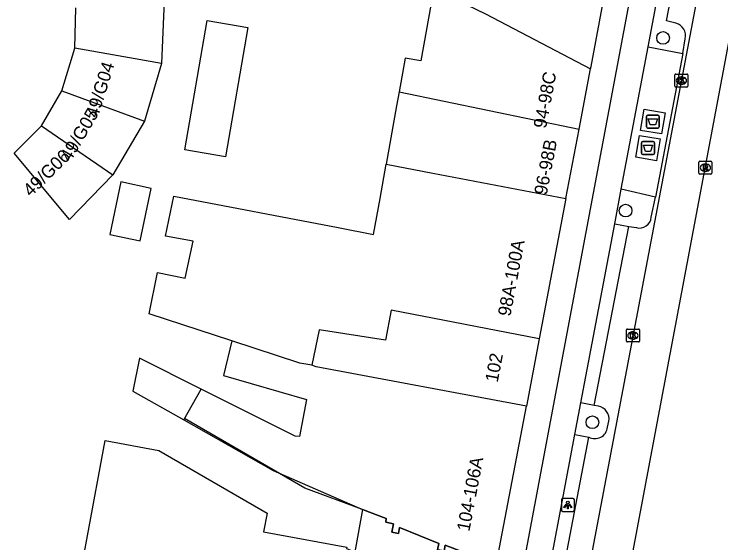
# Model space of a CAD drawing. Extents: x 161402 to 161933, y 381650 to 382313.
# Drawn here: x 161821 to 161875.5, y 381796.3 to 381837.1 of the extents above; entities that cross this region are included whole.
import ezdxf

# ---------------------------------------------------------------- set-up
doc = ezdxf.new("R2010")
doc.units = 0
for name, color, linetype in [('IMGEO_Afval_apart_plaats', 7, 'Continuous'), ('IMGEO_Berm_open', 7, 'Continuous'), ('IMGEO_Boom', 7, 'Continuous'), ('IMGEO_Fietspad_gesloten', 7, 'Continuous'), ('IMGEO_Hek', 7, 'Continuous'), ('IMGEO_Kolk', 7, 'Continuous'), ('IMGEO_Lichtpunt', 7, 'Continuous'), ('IMGEO_OVBaan_gesloten', 7, 'Continuous'), ('IMGEO_Pand', 7, 'Continuous'), ('IMGEO_Pand_nummerreeks', 7, 'Continuous'), ('IMGEO_Pand_overbouw', 7, 'Continuous'), ('IMGEO_Parkeervlak_open', 7, 'Continuous'), ('IMGEO_Rijbaan_lokaal_gesloten', 7, 'Continuous'), ('IMGEO_Rioolput', 7, 'Continuous'), ('IMGEO_Voetpad_gesloten', 7, 'Continuous'), ('IMGEO_Voetpad_open', 7, 'Continuous')]:
    doc.layers.add(name, color=color, linetype=linetype)

msp = doc.modelspace()

# ---------------------------------------------------------------- linework, layer by layer
at = {"layer": 'IMGEO_Afval_apart_plaats'}
for p, q in [((161869.774, 381828.434), (161869.774, 381829.234)), ((161869.774, 381829.234), (161869.774, 381828.434)), ((161869.874, 381829.334), (161870.664, 381829.334)), ((161870.664, 381829.334), (161869.874, 381829.334)), ((161870.764, 381829.234), (161870.764, 381828.434)), ((161870.764, 381828.434), (161870.764, 381829.234)), ((161870.664, 381828.334), (161869.874, 381828.334)), ((161869.874, 381828.334), (161870.664, 381828.334)), ((161869.4, 381826.391), (161869.4, 381827.191)), ((161869.4, 381827.191), (161869.4, 381826.391)), ((161869.5, 381827.291), (161870.29, 381827.291)), ((161870.29, 381827.291), (161869.5, 381827.291)), ((161870.39, 381827.191), (161870.39, 381826.391)), ((161870.39, 381826.391), (161870.39, 381827.191)), ((161870.29, 381826.291), (161869.5, 381826.291)), ((161869.5, 381826.291), (161870.29, 381826.291))]:
    msp.add_line(p, q, dxfattribs=at)
for points in [[(161869.917, 381829.048), (161870.621, 381829.048), (161870.472, 381828.578), (161870.066, 381828.578), (161869.917, 381829.048)], [(161869.543, 381827.005), (161870.247, 381827.005), (161870.098, 381826.535), (161869.692, 381826.535), (161869.543, 381827.005)]]:
    msp.add_lwpolyline(points, dxfattribs=at)
for centre, start, end in [((161869.874, 381829.234), 90, 180), ((161869.874, 381829.234), 90, 180), ((161870.664, 381829.234), 0, 90), ((161870.664, 381829.234), 360, 90), ((161869.874, 381828.434), 180, 270), ((161869.874, 381828.434), 180, 270), ((161870.664, 381828.434), 270, 0), ((161870.664, 381828.434), 270, 0), ((161869.5, 381827.191), 90, 180), ((161869.5, 381827.191), 90, 180), ((161870.29, 381827.191), 0, 90), ((161870.29, 381827.191), 360, 90), ((161869.5, 381826.391), 180, 270), ((161869.5, 381826.391), 180, 270), ((161870.29, 381826.391), 270, 0), ((161870.29, 381826.391), 270, 0)]:
    msp.add_arc(centre, 0.1, start, end, dxfattribs=at)
at = {"layer": 'IMGEO_Berm_open'}
for points in [[(161867.323, 381820.954), (161868.41, 381820.749)], [(161865.742, 381806.939), (161864.714, 381807.133)], [(161864.254, 381804.698), (161865.316, 381804.498)]]:
    msp.add_lwpolyline(points, dxfattribs=at)
at = {"layer": 'IMGEO_Boom'}
for centre in [(161871.055, 381835.287), (161868.169, 381821.967), (161865.604, 381805.641)]:
    msp.add_circle(centre, 0.489, dxfattribs=at)
at = {"layer": 'IMGEO_Fietspad_gesloten'}
for points in [[(161869.899, 381834.602), (161881.54, 381896.271), (161882.623, 381902.093), (161888.398, 381933.147), (161890.059, 381942.083), (161900.83, 382000), (161908.061, 382038.88), (161912.039, 382060.567)], [(161886.669, 381935.154), (161880.56, 381902.497), (161879.486, 381896.758), (161857.65, 381780.798), (161851.928, 381750), (161842.232, 381697.819)], [(161867.824, 381823.608), (161869.899, 381834.602)], [(161867.323, 381820.954), (161867.824, 381823.608)], [(161864.714, 381807.133), (161867.323, 381820.954)], [(161864.254, 381804.698), (161864.714, 381807.133)], [(161844.249, 381697.445), (161849.541, 381725.922), (161850.643, 381731.85), (161854.016, 381750), (161859.509, 381779.56), (161864.254, 381804.698)]]:
    msp.add_lwpolyline(points, dxfattribs=at)
at = {"layer": 'IMGEO_Hek'}
msp.add_lwpolyline([(161847.86, 381798.902), (161843.405, 381800.565), (161834.122, 381805.937)], dxfattribs=at)
at = {"layer": 'IMGEO_Kolk'}
for p, q in [((161871.971, 381831.573), (161871.971, 381832.425)), ((161872.046, 381832.499), (161872.898, 381832.499)), ((161872.972, 381832.425), (161872.972, 381831.573)), ((161872.459, 381832.279), (161872.484, 381832.279)), ((161872.898, 381831.499), (161872.046, 381831.499)), ((161872.482, 381831.719), (161872.457, 381831.719)), ((161868.225, 381811.906), (161868.225, 381812.758)), ((161868.3, 381812.832), (161869.152, 381812.832)), ((161869.226, 381812.758), (161869.226, 381811.906)), ((161868.713, 381812.612), (161868.738, 381812.612)), ((161869.152, 381811.832), (161868.3, 381811.832)), ((161868.736, 381812.052), (161868.711, 381812.052))]:
    msp.add_line(p, q, dxfattribs=at)
for points in [[(161871.971, 381831.573), (161871.971, 381832.425)], [(161872.046, 381832.499), (161872.898, 381832.499)], [(161872.972, 381832.425), (161872.972, 381831.573)], [(161872.292, 381832.199), (161872.415, 381832.199), (161872.415, 381832.048), (161872.545, 381832.199), (161872.709, 381832.199), (161872.563, 381832.048), (161872.716, 381831.799), (161872.564, 381831.799), (161872.479, 381831.963), (161872.415, 381831.896), (161872.415, 381831.799), (161872.292, 381831.799), (161872.292, 381832.199)], [(161872.898, 381831.499), (161872.046, 381831.499)], [(161868.225, 381811.906), (161868.225, 381812.758)], [(161868.3, 381812.832), (161869.152, 381812.832)], [(161869.226, 381812.758), (161869.226, 381811.906)], [(161868.546, 381812.532), (161868.669, 381812.532), (161868.669, 381812.381), (161868.799, 381812.532), (161868.963, 381812.532), (161868.817, 381812.381), (161868.97, 381812.132), (161868.818, 381812.132), (161868.733, 381812.296), (161868.669, 381812.229), (161868.669, 381812.132), (161868.546, 381812.132), (161868.546, 381812.532)], [(161869.152, 381811.832), (161868.3, 381811.832)]]:
    msp.add_lwpolyline(points, dxfattribs=at)
for centre, start, end in [((161872.048, 381832.423), 91.552, 178.448), ((161872.048, 381832.423), 91.552, 178.448), ((161872.896, 381832.423), 1.552, 88.448), ((161872.896, 381832.423), 1.552, 88.448), ((161872.048, 381831.575), 181.552, 268.448), ((161872.048, 381831.575), 181.552, 268.448), ((161872.896, 381831.575), 271.552, 358.448), ((161872.896, 381831.575), 271.552, 358.448), ((161868.302, 381812.756), 91.552, 178.448), ((161868.302, 381812.756), 91.552, 178.448), ((161869.15, 381812.756), 1.552, 88.448), ((161869.15, 381812.756), 1.552, 88.448), ((161868.302, 381811.908), 181.552, 268.448), ((161868.302, 381811.908), 181.552, 268.448), ((161869.15, 381811.908), 271.552, 358.448), ((161869.15, 381811.908), 271.552, 358.448)]:
    msp.add_arc(centre, 0.0765, start, end, dxfattribs=at)
for centre, major_axis, ratio, start_param, end_param in [((161872.458, 381831.999), (-0.387, 0.002), 0.722429, 4.712389, 7.853982), ((161872.483, 381831.999), (-0.39, 0.002), 0.717154, 1.570796, 4.712389), ((161868.712, 381812.332), (-0.387, 0.002), 0.722429, 4.712389, 7.853982), ((161868.737, 381812.332), (-0.39, 0.002), 0.717154, 1.570796, 4.712389)]:
    msp.add_ellipse(centre, major_axis=major_axis, ratio=ratio, start_param=start_param, end_param=end_param, dxfattribs=at)
at = {"layer": 'IMGEO_Lichtpunt'}
for p, q in [((161863.212, 381799.659), (161863.212, 381798.852)), ((161863.212, 381799.659), (161863.212, 381798.852)), ((161864.114, 381799.754), (161863.306, 381799.754)), ((161864.114, 381799.754), (161863.306, 381799.754)), ((161864.208, 381798.852), (161864.208, 381799.659)), ((161864.208, 381798.852), (161864.208, 381799.659)), ((161863.306, 381798.758), (161864.114, 381798.758)), ((161863.306, 381798.758), (161864.114, 381798.758))]:
    msp.add_line(p, q, dxfattribs=at)
for points in [[(161863.586, 381799.323), (161863.625, 381799.295), (161863.437, 381799.033), (161863.399, 381799.06), (161863.586, 381799.323)], [(161863.688, 381799.275), (161863.735, 381799.275), (161863.735, 381798.953), (161863.688, 381798.953), (161863.688, 381799.275)], [(161863.798, 381799.295), (161863.836, 381799.322), (161864.023, 381799.06), (161863.984, 381799.032), (161863.798, 381799.295)]]:
    msp.add_lwpolyline(points, dxfattribs=at)
msp.add_circle((161863.711, 381799.457), 0.0994, dxfattribs=at)
for centre, start, end in [((161863.306, 381799.659), 90, 180), ((161863.306, 381799.659), 90, 180), ((161864.114, 381799.659), 0, 90), ((161864.114, 381799.659), 0, 90), ((161863.306, 381798.852), 180, 270), ((161863.306, 381798.852), 180, 270), ((161864.114, 381798.852), 270, 0), ((161864.114, 381798.852), 270, 360)]:
    msp.add_arc(centre, 0.0946, start, end, dxfattribs=at)
at = {"layer": 'IMGEO_OVBaan_gesloten'}
msp.add_lwpolyline([(161866.208, 381782.197), (161889.963, 381908.334)], dxfattribs=at)
at = {"layer": 'IMGEO_Pand'}
for points in [[(161865.464, 381832.9), (161865.498, 381833.078), (161871.236, 381863.835)], [(161853.347, 381839.11), (161852.346, 381833.514), (161851.141, 381833.729), (161850.676, 381831.127)], [(161853.347, 381839.11), (161853.718, 381838.91), (161857.352, 381837.151), (161865.464, 381832.9)], [(161832.532, 381838.148), (161832.326, 381833.3)], [(161825.632, 381834.487), (161825.716, 381837.606)], [(161835.87, 381836.631), (161839.006, 381836.083), (161837.262, 381826.104), (161834.125, 381826.652), (161835.87, 381836.631)], [(161824.629, 381831.199), (161825.632, 381834.487)], [(161832.326, 381833.3), (161825.632, 381834.487)], [(161832.326, 381833.3), (161831.022, 381828.853)], [(161864.577, 381828.237), (161865.464, 381832.9)], [(161823.067, 381828.511), (161824.629, 381831.199)], [(161824.629, 381831.199), (161831.022, 381828.853)], [(161850.676, 381831.127), (161850.483, 381830.049), (161849.676, 381825.535)], [(161850.676, 381831.127), (161864.577, 381828.237)], [(161828.579, 381824.737), (161825.227, 381821.282), (161820.956, 381826.404), (161823.067, 381828.511)], [(161823.067, 381828.511), (161828.579, 381824.737)], [(161831.022, 381828.853), (161828.579, 381824.737)], [(161863.56, 381822.895), (161864.577, 381828.237)], [(161837.762, 381811.919), (161831.384, 381813.997), (161832.023, 381817.194), (161834.166, 381816.745), (161834.791, 381819.599), (161832.631, 381819.995), (161833.279, 381823.092), (161845.982, 381820.657), (161848.712, 381820.134), (161849.205, 381822.897), (161849.676, 381825.535)], [(161849.676, 381825.535), (161853.274, 381824.851), (161863.56, 381822.895)], [(161828.333, 381820.119), (161830.698, 381819.624), (161831.547, 381823.681), (161829.182, 381824.176), (161828.333, 381820.119)], [(161863.56, 381822.895), (161861.5, 381812.067)], [(161861.5, 381812.067), (161850.068, 381814.292), (161849.633, 381811.975), (161844.516, 381812.77), (161843.941, 381810.032)], [(161837.762, 381811.919), (161837.118, 381809.253), (161843.522, 381807.394), (161842.986, 381804.544), (161842.647, 381804.557), (161835.39, 381808.201)], [(161843.941, 381810.032), (161843.015, 381810.207), (161837.762, 381811.919)], [(161861.5, 381812.067), (161860.511, 381806.869)], [(161835.39, 381808.201), (161830.633, 381810.59), (161830.124, 381808.048), (161834.057, 381805.821)], [(161860.511, 381806.869), (161844.279, 381809.92), (161843.941, 381810.032)], [(161834.057, 381805.821), (161835.39, 381808.201)], [(161858.115, 381794.262), (161858.21, 381794.775), (161860.511, 381806.869)], [(161834.057, 381805.821), (161840.962, 381801.911), (161847.86, 381798.902), (161849.682, 381798.222), (161849.663, 381797.923), (161850.239, 381797.804), (161850.117, 381797.158), (161850.627, 381797.062), (161850.716, 381797.533), (161853.746, 381796.3), (161853.653, 381795.807), (161854.154, 381795.713), (161854.239, 381796.167), (161857.521, 381794.895), (161857.427, 381794.392), (161858.115, 381794.262)], [(161841.091, 381786.52), (161825.253, 381789.517), (161827.976, 381804.229), (161832.124, 381803.461), (161840.482, 381798.624), (161840.218, 381797.195), (161846.644, 381796.006), (161846.624, 381795.895), (161847.248, 381795.649), (161851.239, 381794.077), (161851.163, 381793.987), (161851.433, 381793.88), (161856.08, 381792.037), (161856.9, 381790.844), (161856.653, 381789.512), (161857.009, 381789.446)]]:
    msp.add_lwpolyline(points, dxfattribs=at)
at = {"layer": 'IMGEO_Pand_overbouw'}
msp.add_lwpolyline([(161857.009, 381789.446), (161858.115, 381794.262), (161857.427, 381794.392), (161857.521, 381794.895), (161854.239, 381796.167), (161854.154, 381795.713), (161853.653, 381795.807), (161853.746, 381796.3), (161850.716, 381797.533), (161850.627, 381797.062), (161850.117, 381797.158), (161850.239, 381797.804), (161849.663, 381797.923), (161849.682, 381798.222), (161847.86, 381798.902), (161847.248, 381795.649), (161851.239, 381794.077), (161851.163, 381793.987), (161851.433, 381793.88), (161856.08, 381792.037), (161856.9, 381790.844), (161856.653, 381789.512)], close=True, dxfattribs=at)
at = {"layer": 'IMGEO_Parkeervlak_open'}
for points in [[(161872.047, 381836.423), (161871.323, 381836.592), (161873.371, 381847.295), (161873.66, 381847.251)], [(161872.587, 381834.08), (161872.769, 381835.211)], [(161870.147, 381821.456), (161870.482, 381822.992)], [(161865.742, 381806.939), (161868.41, 381820.749)], [(161868.41, 381820.749), (161868.995, 381820.652)], [(161866.06, 381806.892), (161865.742, 381806.939)], [(161866.768, 381805.264), (161866.881, 381805.727)], [(161860.529, 381779.475), (161865.316, 381804.498)]]:
    msp.add_lwpolyline(points, dxfattribs=at)
for centre, radius, start, end in [((161871.795, 381835.452), 1.004, 346.1316, 75.4337), ((161869.235, 381821.536), 0.916, 254.8254, 354.9982), ((161865.846, 381805.869), 1.045, 352.1838, 78.1625), ((161865.789, 381805.36), 0.983, 241.2166, 354.411)]:
    msp.add_arc(centre, radius, start, end, dxfattribs=at)
at = {"layer": 'IMGEO_Rijbaan_lokaal_gesloten'}
msp.add_lwpolyline([(161884.15, 381893.504), (161864.093, 381787.863), (161863.613, 381786.178), (161863.081, 381785.029), (161862.376, 381783.945), (161861.521, 381781.789), (161860.529, 381779.475)], dxfattribs=at)
at = {"layer": 'IMGEO_Rioolput'}
for p, q in [((161873.901, 381825.773), (161874.753, 381825.773)), ((161873.826, 381824.847), (161873.826, 381825.699)), ((161874.314, 381825.553), (161874.339, 381825.553)), ((161874.827, 381825.699), (161874.827, 381824.847)), ((161874.753, 381824.773), (161873.901, 381824.773)), ((161874.337, 381824.993), (161874.312, 381824.993))]:
    msp.add_line(p, q, dxfattribs=at)
for points in [[(161873.901, 381825.773), (161874.753, 381825.773)], [(161873.826, 381824.847), (161873.826, 381825.699)], [(161874.415, 381825.471), (161874.163, 381825.473), (161874.163, 381825.073)], [(161874.163, 381825.073), (161874.287, 381825.073), (161874.287, 381825.235), (161874.298, 381825.235)], [(161874.341, 381825.392), (161874.287, 381825.392), (161874.287, 381825.311)], [(161874.287, 381825.311), (161874.339, 381825.311)], [(161874.827, 381825.699), (161874.827, 381824.847)], [(161874.753, 381824.773), (161873.901, 381824.773)], [(161874.345, 381825.206), (161874.416, 381825.073), (161874.556, 381825.073), (161874.491, 381825.199)]]:
    msp.add_lwpolyline(points, dxfattribs=at)
for centre, radius, start, end in [((161873.903, 381825.697), 0.0765, 91.552, 178.448), ((161873.903, 381825.697), 0.0765, 91.552, 178.448), ((161874.751, 381825.697), 0.0765, 1.552, 88.448), ((161874.751, 381825.697), 0.0765, 1.552, 88.448), ((161874.297, 381825.182), 0.0533, 26.0293, 88.6989), ((161874.323, 381825.5), 0.19, 274.7715, 282.9687), ((161874.347, 381825.296), 0.0964, 77.0061, 93.1865), ((161874.361, 381825.353), 0.0378, 276.6634, 79.6772), ((161874.414, 381825.361), 0.109, 350.3612, 89.416), ((161874.412, 381825.361), 0.112, 277.5842, 350.9817), ((161874.396, 381825.146), 0.108, 29.5134, 73.7905), ((161873.903, 381824.849), 0.0765, 181.552, 268.448), ((161873.903, 381824.849), 0.0765, 181.552, 268.448), ((161874.751, 381824.849), 0.0765, 271.552, 358.448), ((161874.751, 381824.849), 0.0765, 271.552, 358.448)]:
    msp.add_arc(centre, radius, start, end, dxfattribs=at)
for centre, major_axis, ratio, start_param, end_param in [((161874.313, 381825.273), (-0.387, 0.002), 0.722429, 4.712389, 7.853982), ((161874.338, 381825.273), (-0.39, 0.002), 0.717154, 1.570796, 4.712389)]:
    msp.add_ellipse(centre, major_axis=major_axis, ratio=ratio, start_param=start_param, end_param=end_param, dxfattribs=at)
at = {"layer": 'IMGEO_Voetpad_gesloten'}
for points in [[(161871.222, 381829.513), (161870.938, 381827.875), (161869.316, 381828.156), (161869.6, 381829.794), (161871.222, 381829.513)], [(161870.826, 381827.506), (161870.544, 381825.814), (161868.964, 381826.077), (161869.246, 381827.769), (161870.826, 381827.506)]]:
    msp.add_lwpolyline(points, dxfattribs=at)
at = {"layer": 'IMGEO_Voetpad_open'}
for points in [[(161869.899, 381834.602), (161872.587, 381834.08)], [(161872.587, 381834.08), (161870.482, 381822.992)], [(161870.482, 381822.992), (161867.824, 381823.608)]]:
    msp.add_lwpolyline(points, dxfattribs=at)

# ---------------------------------------------------------------- texts
at = {"layer": 'IMGEO_Pand_nummerreeks'}
for s, rotation, p in [('49/G04', 72.646, (161827.413, 381829.06)), ('94-98C', 79.4521, (161862.022, 381828.258)), ('49/G05', 59.5345, (161825.298, 381825.671)), ('96-98B', 79.2229, (161862.075, 381823.116)), ('49/G06', 44.4645, (161822.24, 381822.983)), ('98A-100A', 79.2859, (161859.271, 381813.764)), ('102', 79.2274, (161858.289, 381808.672)), ('104-106A', 79.2286, (161856.101, 381797.17))]:
    msp.add_text(s, height=1, rotation=rotation, dxfattribs=at).set_placement(p)

doc.saveas('drawing.dxf')
